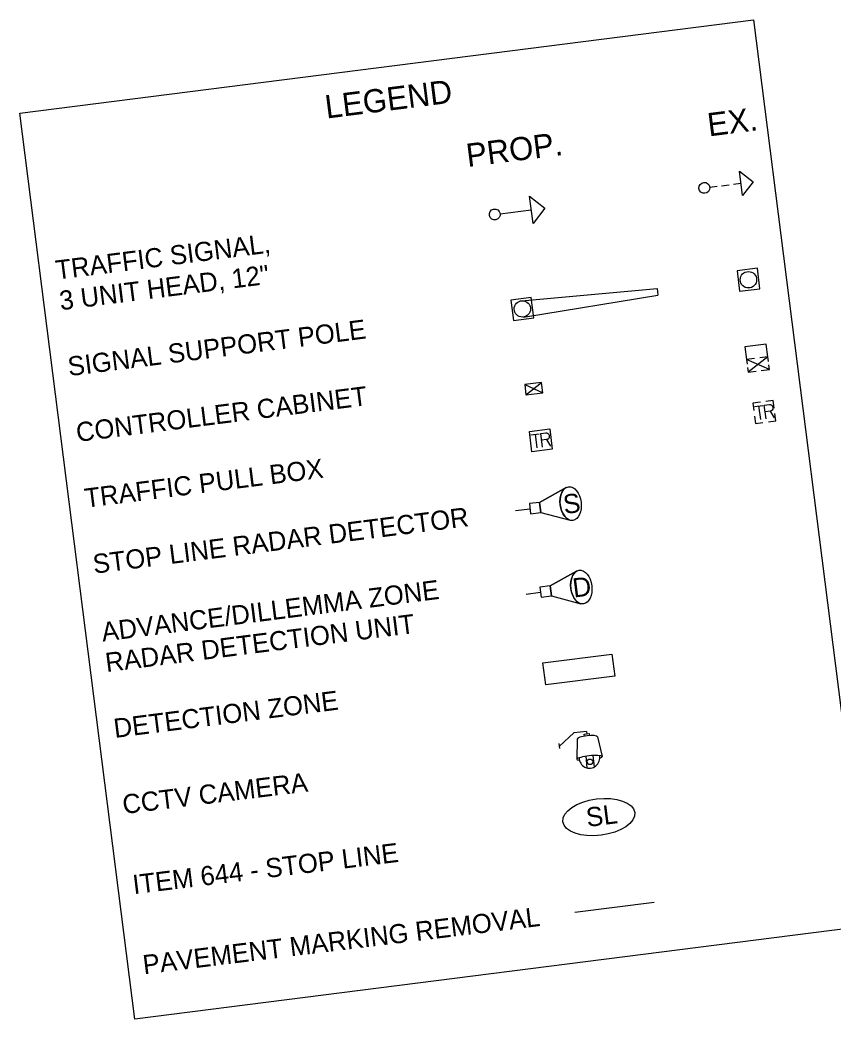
# Model space of a CAD drawing. Extents: x 1509453 to 1510107, y 694919 to 695353.
# Drawn here: x 1509453.1 to 1509572, y 695164.3 to 695310.3 of the extents above; entities that cross this region are included whole.
import ezdxf

# ---------------------------------------------------------------- set-up
doc = ezdxf.new("R2010")
doc.units = 0
for name, color, linetype in [('RW_X_CL', 7, 'Continuous'), ('SG_P_Controllers', 7, 'Continuous'), ('SG_P_Detection', 7, 'Continuous'), ('SG_P_Heads', 7, 'Continuous'), ('SG_P_Interconnect_Cable', 7, 'Continuous'), ('SG_X_Controllers', 7, 'Continuous'), ('SG_X_Heads', 7, 'Continuous'), ('SG_X_PullBox', 7, 'Continuous'), ('SH_Border', 7, 'Continuous'), ('SH_Text', 7, 'Continuous'), ('SN_P_Text', 7, 'Continuous'), ('UT_X_Sanitary_Cells', 7, 'Continuous')]:
    doc.layers.add(name, color=color, linetype=linetype)

msp = doc.modelspace()

# ---------------------------------------------------------------- linework, layer by layer
at = {"layer": 'RW_X_CL'}
for p, q in [((1509562.49, 695261.03), (1509559.63, 695258.77)), ((1509562.73, 695259.17), (1509559.39, 695260.63)), ((1509561.06, 695259.9), (1509561.06, 695259.9))]:
    msp.add_line(p, q, dxfattribs=at)
for points in [[(1509562.49, 695261.03), (1509562.26, 695262.89), (1509559.16, 695262.49), (1509559.39, 695260.63)], [(1509562.58, 695260.34), (1509562.49, 695261.03), (1509561.32, 695260.88)], [(1509560.57, 695260.78), (1509559.39, 695260.63), (1509559.48, 695259.95)], [(1509559.54, 695259.46), (1509559.63, 695258.77), (1509560.81, 695258.92)], [(1509561.55, 695259.02), (1509562.73, 695259.17), (1509562.64, 695259.85)]]:
    msp.add_lwpolyline(points, dxfattribs=at)
at = {"layer": 'SG_P_Controllers'}
for p, q in [((1509529.12, 695239.77), (1509533, 695241.93)), ((1509533, 695241.93), (1509529.12, 695239.77)), ((1509529.12, 695239.77), (1509529.31, 695238.29)), ((1509525.62, 695238.57), (1509527.73, 695238.84)), ((1509529.31, 695238.29), (1509533.6, 695237.16)), ((1509529.31, 695238.29), (1509533.6, 695237.16)), ((1509530.67, 695227.57), (1509534.54, 695229.73)), ((1509534.54, 695229.73), (1509530.67, 695227.57)), ((1509530.67, 695227.57), (1509530.86, 695226.09)), ((1509530.86, 695226.09), (1509530.67, 695227.57)), ((1509527.17, 695226.37), (1509529.28, 695226.64)), ((1509530.86, 695226.09), (1509535.15, 695224.96)), ((1509530.86, 695226.09), (1509535.15, 695224.96)), ((1509535.99, 695206.31), (1509536.03, 695205.94)), ((1509537.59, 695205.51), (1509538.28, 695202.64)), ((1509532.07, 695203.79), (1509531.99, 695204.54)), ((1509534.61, 695205.18), (1509534.56, 695202.22)), ((1509535.87, 695202.66), (1509536.06, 695200.98)), ((1509536.91, 695202.78), (1509537.1, 695201.09))]:
    msp.add_line(p, q, dxfattribs=at)
for points in [[(1509527.63, 695239.58), (1509527.82, 695238.1), (1509529.31, 695238.29), (1509529.12, 695239.77)], [(1509529.18, 695227.38), (1509529.37, 695225.9), (1509530.86, 695226.09), (1509530.67, 695227.57)], [(1509529.62, 695216.31), (1509539.7, 695217.59), (1509540.11, 695214.38), (1509530.03, 695213.11)]]:
    msp.add_lwpolyline(points, close=True, dxfattribs=at)
for points in [[(1509527.63, 695239.58), (1509527.82, 695238.1), (1509529.31, 695238.29), (1509529.12, 695239.77), (1509527.63, 695239.58)], [(1509530.67, 695227.57), (1509529.18, 695227.38), (1509529.37, 695225.9), (1509530.86, 695226.09)], [(1509535.99, 695206.31), (1509534.13, 695206.1), (1509532.03, 695204.16)], [(1509535.69, 695205.6), (1509535.66, 695205.89), (1509536.4, 695205.98), (1509536.44, 695205.68)]]:
    msp.add_lwpolyline(points, dxfattribs=at)
for centre, major_axis, ratio in [((1509533.67, 695239.59), (0.31, -2.46), 0.621318), ((1509535.22, 695227.39), (0.31, -2.46), 0.621318), ((1509536.49, 695201.86), (-0.013, 0.409), 0.999249)]:
    msp.add_ellipse(centre, major_axis=major_axis, ratio=ratio, dxfattribs=at)
for centre, major_axis, ratio, start_param, end_param in [((1509533.67, 695239.59), (0.31, -2.46), 0.621318, 3.386213, 6.038231), ((1509535.22, 695227.39), (0.31, -2.46), 0.621318, 3.386213, 6.038231), ((1509536.1, 695205.35), (1.49, 0.17), 0.200149, 6.283161, 9.424753), ((1509536.42, 695202.43), (1.86, 0.21), 0.160119, 5.62984, 10.078084), ((1509536.42, 695202.43), (-0.05, 1.5), 0.999249, 1.527523, 4.912851)]:
    msp.add_ellipse(centre, major_axis=major_axis, ratio=ratio, start_param=start_param, end_param=end_param, dxfattribs=at)
at = {"layer": 'SG_P_Detection'}
for p, q in [((1509526.46, 695269.22), (1509546.3, 695271.02)), ((1509546.3, 695271.02), (1509546.43, 695270.04)), ((1509526.76, 695266.84), (1509546.43, 695270.04))]:
    msp.add_line(p, q, dxfattribs=at)
msp.add_lwpolyline([(1509525.32, 695266.35), (1509528.29, 695266.73), (1509527.91, 695269.71), (1509524.94, 695269.33)], close=True, dxfattribs=at)
msp.add_ellipse((1509526.61, 695268.03), major_axis=(-0.25, 1.17), ratio=0.999249, dxfattribs=at)
at = {"layer": 'SG_P_Heads'}
msp.add_line((1509529.31, 695248.82), (1509529.31, 695248.82), dxfattribs=at)
msp.add_lwpolyline([(1509527.64, 695250.12), (1509530.61, 695250.49), (1509530.99, 695247.52), (1509528.01, 695247.14)], close=True, dxfattribs=at)
for points in [[(1509527.84, 695249.64), (1509529.07, 695249.79)], [(1509528.47, 695249.72), (1509528.72, 695247.73)], [(1509529.55, 695247.84), (1509529.3, 695249.82), (1509530.05, 695249.92), (1509530.13, 695249.91), (1509530.24, 695249.89), (1509530.29, 695249.87), (1509530.34, 695249.84), (1509530.41, 695249.77), (1509530.47, 695249.7), (1509530.52, 695249.58), (1509530.54, 695249.39), (1509530.53, 695249.33), (1509530.51, 695249.23), (1509530.46, 695249.11), (1509530.41, 695249.06), (1509530.37, 695249.02), (1509530.34, 695249), (1509530.29, 695248.98), (1509530.15, 695248.95), (1509529.42, 695248.85)], [(1509530.15, 695248.95), (1509530.72, 695247.99)]]:
    msp.add_lwpolyline(points, dxfattribs=at)
at = {"layer": 'SG_P_Interconnect_Cable'}
msp.add_lwpolyline([(1509558.37, 695270.62), (1509561.35, 695270.99), (1509560.97, 695273.97), (1509558, 695273.59)], close=True, dxfattribs=at)
msp.add_circle((1509559.67, 695272.29), 1.2, dxfattribs=at)
at = {"layer": 'SG_X_Controllers'}
msp.add_line((1509562, 695252.96), (1509562, 695252.96), dxfattribs=at)
for points in [[(1509561.42, 695254.4), (1509560.33, 695254.26), (1509560.46, 695253.17)], [(1509560.53, 695253.78), (1509561.77, 695253.94)], [(1509561.16, 695253.86), (1509561.41, 695251.88)], [(1509562.24, 695251.98), (1509561.99, 695253.97), (1509562.74, 695254.06), (1509562.82, 695254.06), (1509562.93, 695254.04), (1509562.98, 695254.01), (1509563.03, 695253.99), (1509563.11, 695253.92), (1509563.16, 695253.85), (1509563.21, 695253.73), (1509563.23, 695253.54), (1509563.23, 695253.47), (1509563.21, 695253.38), (1509563.16, 695253.26), (1509563.1, 695253.2), (1509563.06, 695253.17), (1509563.03, 695253.15), (1509562.98, 695253.13), (1509562.85, 695253.09), (1509562.11, 695253)], [(1509563.44, 695253.55), (1509563.3, 695254.64), (1509562.21, 695254.5)], [(1509560.57, 695252.38), (1509560.7, 695251.28), (1509561.79, 695251.42)], [(1509562.59, 695251.52), (1509563.68, 695251.66), (1509563.54, 695252.75)], [(1509562.85, 695253.09), (1509563.41, 695252.13)]]:
    msp.add_lwpolyline(points, dxfattribs=at)
at = {"layer": 'SG_X_Heads'}
for p, q in [((1509526.95, 695256.97), (1509529.62, 695255.79)), ((1509527.13, 695255.48), (1509529.43, 695257.28))]:
    msp.add_line(p, q, dxfattribs=at)
msp.add_lwpolyline([(1509527.13, 695255.48), (1509529.62, 695255.79), (1509529.43, 695257.28), (1509526.95, 695256.97), (1509527.13, 695255.48)], dxfattribs=at)
at = {"layer": 'SG_X_PullBox'}
msp.add_line((1509523.36, 695281.93), (1509527.92, 695282.51), dxfattribs=at)
msp.add_lwpolyline([(1509527.67, 695284.49), (1509529.9, 695282.76), (1509528.17, 695280.52)], close=True, dxfattribs=at)
msp.add_ellipse((1509522.57, 695281.83), major_axis=(-0.166, 0.783), ratio=0.999249, dxfattribs=at)
at = {"layer": 'SH_Border'}
msp.add_lwpolyline([(1509453.15, 695296.65), (1509560.43, 695310.25), (1509577.22, 695177.88), (1509469.93, 695164.28)], close=True, dxfattribs=at)
at = {"layer": 'SH_Text'}
msp.add_ellipse((1509537.79, 695193.78), major_axis=(5.25, 0.67), ratio=0.505596, dxfattribs=at)
at = {"layer": 'SN_P_Text'}
for p, q in [((1509554.01, 695285.82), (1509555.1, 695285.96)), ((1509555.75, 695286.04), (1509556.84, 695286.18)), ((1509557.48, 695286.26), (1509558.57, 695286.4))]:
    msp.add_line(p, q, dxfattribs=at)
msp.add_lwpolyline([(1509558.35, 695288.18), (1509560.36, 695286.62), (1509558.8, 695284.61)], close=True, dxfattribs=at)
msp.add_ellipse((1509553.22, 695285.72), major_axis=(0.797, 0.072), ratio=0.997574, dxfattribs=at)
at = {"layer": 'UT_X_Sanitary_Cells'}
msp.add_line((1509534.3, 695179.9), (1509545.86, 695181.37), dxfattribs=at)

# ---------------------------------------------------------------- texts
at = {"layer": 'SG_P_Controllers'}
for s, rotation, p in [('S', 7.227, (1509532.76, 695238.06)), ('D', 7.2497, (1509534.14, 695225.85))]:
    msp.add_text(s, height=2.8, rotation=rotation, dxfattribs=at).set_placement(p)
at = {"layer": 'SH_Text'}
for s, height, rotation, p in [('LEGEND', 3.4, 7.227, (1509497.97, 695295.84)), ('EX.', 3.4, 7.227, (1509553.89, 695293.23)), ('PROP.', 3.4, 7.227, (1509518.62, 695288.76)), ('TRAFFIC SIGNAL,', 2.8, 7.227, (1509458.54, 695272.3)), ('3 UNIT HEAD, 12"', 2.8, 7.227, (1509459.1, 695267.83)), ('SIGNAL SUPPORT POLE', 2.8, 7.227, (1509460.32, 695258.21)), ('CONTROLLER CABINET', 2.8, 7.227, (1509461.54, 695248.59)), ('TRAFFIC PULL BOX ', 2.8, 7.227, (1509462.77, 695238.97)), ('STOP LINE RADAR DETECTOR', 2.8, 7.227, (1509463.99, 695229.34)), ('ADVANCE/DILLEMMA ZONE', 2.8, 7.227, (1509465.25, 695219.42)), ('RADAR DETECTION UNIT', 2.8, 7.227, (1509465.81, 695214.96)), ('DETECTION ZONE', 2.8, 7.227, (1509467.03, 695205.34)), ('CCTV CAMERA', 2.8, 6.9584, (1509468.31, 695194.22)), ('SL', 2.8, 7.227, (1509536.11, 695192.33)), ('ITEM 644 - STOP LINE', 2.8, 6.9584, (1509469.8, 695182.51)), ('PAVEMENT MARKING REMOVAL', 2.8, 6.9584, (1509471.28, 695170.8))]:
    msp.add_text(s, height=height, rotation=rotation, dxfattribs=at).set_placement(p)

doc.saveas('drawing.dxf')
